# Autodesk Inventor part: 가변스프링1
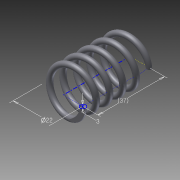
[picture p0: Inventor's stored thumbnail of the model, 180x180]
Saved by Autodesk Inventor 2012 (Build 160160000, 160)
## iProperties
Created: 2015-02
Part Number: 가변스프링1
Material: 탄소강
Document SubType Name: Modeling
Designer: Owner
Mass: 18.7435 g
Surface Area: 32.3808 cm^2
Volume: 2.38164 cm^3
Density: 7.87 g/cm^3
Author: Owner
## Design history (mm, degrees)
sketch "스케치1"
  geometry: L1 (0, 0)-(11, 0); L2 (11, 0)-(11, 25.358); L3 (11, 25.358)-(0, 25.358); L4 (0, 25.358)-(0, 0); C1 r 1.5 at (11, 0)
  constraints: 8 end point, 2 parallel, 1 centre point, 1 coincident, 1 horizontal, 1 perpendicular
  dimensions: "d0" = 22 diameter of L2 L4; "d1" = 25.35829 distance of L1.end L2.end (derived); "d2" = 3 diameter of C1
feature "코일1" pitch "d3" = 10; turns "d5" = 5; dims "d4" = 25.35829 (= d1), "d6" = 0, angle "d7" = 90 deg, angle "d8" = 90 deg, "d9" = 0, "d10" = 0
sketch "스케치2"
  geometry: L1 (-12.5, 0)-(-9.5, 0) reference; 1 further point
  constraints: 1 horizontal alignment
extrude "돌출1" cut sketch "스케치2" stored distance "d11" = 10; taper "d12" = 0 deg
node "작업 평면1"
sketch "스케치3"
  geometry: L1 (-9.5, 0)-(-12.5, 0) reference; 1 further point
  constraints: 1 horizontal alignment
extrude "돌출2" cut sketch "스케치3" stored distance "d13" = 10; taper "d14" = 0 deg
node "솔리드1"
node "절단 모서리 투영1"
node "절단 모서리 투영2"
